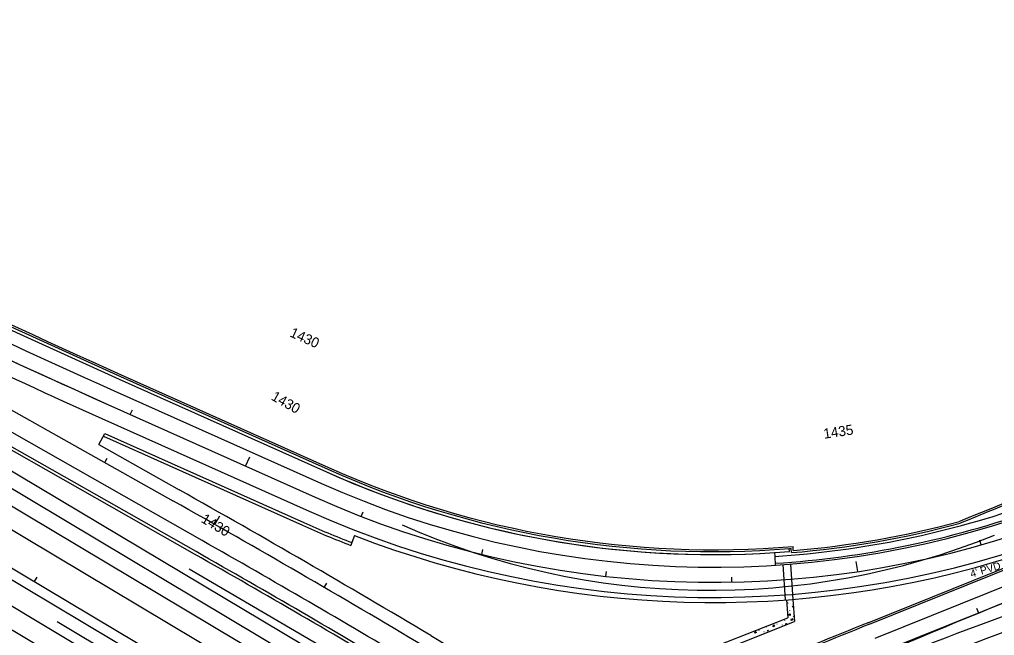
# Model space of a CAD drawing. Extents: x 2339272 to 2351734, y 366540 to 375057.
# Drawn here: x 2349008 to 2349780, y 368209 to 368697 of the extents above; entities that cross this region are included whole.
import ezdxf

# ---------------------------------------------------------------- set-up
doc = ezdxf.new("R2010")
doc.units = 0
for name, color, linetype in [('RD_HC_Cl', 7, 'Continuous'), ('RD_HC_CL_Rel', 7, 'Continuous'), ('RD_HC_Data_Tic', 7, 'Continuous'), ('RD_HC_Data_Tic_Rel', 7, 'Continuous'), ('RD_HC_TX_Rel_Sta50', 7, 'Continuous'), ('RD_HC_TX_Sta50', 7, 'Continuous'), ('RD_PD_Final_LnLine', 7, 'Continuous'), ('RD_PD_Final_TrvlWay', 7, 'Continuous'), ('RD_PD_FOC', 7, 'Continuous'), ('RD_PD_GR', 7, 'Continuous'), ('RD_PD_GrRail', 7, 'Continuous'), ('RD_PD_MedBWall', 7, 'Continuous'), ('RD_PD_MedGR', 7, 'Continuous'), ('RD_PD_NOISE-WALL-GM', 7, 'Continuous'), ('RD_PD_PaveShd', 7, 'Continuous'), ('RD_PD_SW', 7, 'Continuous'), ('RD_PD_WallCut', 7, 'Continuous')]:
    doc.layers.add(name, color=color, linetype=linetype)

msp = doc.modelspace()

# ---------------------------------------------------------------- linework, layer by layer
at = {"layer": 'RD_HC_Cl'}
msp.add_line((2346281.57, 369885.43), (2351112.4, 367003.22), dxfattribs=at)
for centre, radius, start, end in [((2351947.82, 362927.74), 5729.58, 109.588035, 115.940729), ((2349555.53, 368844.49), 600, 245.9774, 292.01473), ((2349555.53, 368844.49), 600, 245.9774, 292.01473), ((2349555.53, 368844.49), 600, 245.9774, 292.01473), ((2349555.53, 368844.49), 600, 245.9774, 292.01473)]:
    msp.add_arc(centre, radius, start, end, dxfattribs=at)
at = {"layer": 'RD_HC_CL_Rel'}
for p, q in [((2348500.93, 368669.16), (2349129.79, 368315.43)), ((2349078.31, 368391.71), (2349242.47, 368318.22))]:
    msp.add_line(p, q, dxfattribs=at)
for centre, radius, start, end in [((2351938.58, 374780.68), 7000, 240.642806, 245.882475), ((2344717.52, 360471.2), 9000, 59.178507, 60.642806), ((2349557.92, 369022.83), 772, 245.88247, 289.58804)]:
    msp.add_arc(centre, radius, start, end, dxfattribs=at)
at = {"layer": 'RD_HC_Data_Tic'}
for p, q in [((2349020.25, 368251.46), (2349022.3, 368254.89)), ((2349767.92, 368226.43), (2349766.4, 368230.13))]:
    msp.add_line(p, q, dxfattribs=at)
at = {"layer": 'RD_HC_Data_Tic_Rel'}
for p, q in [((2349096.07, 368383.76), (2349097.7, 368387.41)), ((2349187.34, 368342.9), (2349190.61, 368350.2)), ((2349075.82, 368345.78), (2349077.78, 368349.27)), ((2349162.94, 368296.69), (2349166.89, 368303.64)), ((2349279.01, 368302.97), (2349280.45, 368306.7)), ((2349769.8, 368280.48), (2349768.7, 368284.32)), ((2349374.33, 368272.98), (2349375.28, 368276.86)), ((2349672.13, 368259.33), (2349670.95, 368267.24)), ((2349472.73, 368255.55), (2349473.17, 368259.52)), ((2349249.62, 368246.81), (2349251.63, 368250.27)), ((2349572.55, 368250.97), (2349572.48, 368254.97))]:
    msp.add_line(p, q, dxfattribs=at)
at = {"layer": 'RD_PD_Final_LnLine'}
for p, q in [((2348620.92, 368538.62), (2351133.92, 367039.29)), ((2348577.88, 368466.48), (2351090.88, 366967.15)), ((2349078.31, 368391.71), (2349242.47, 368318.22)), ((2349612.85, 368264.87), (2349614.76, 368236.93)), ((2349618.83, 368265.28), (2349620.74, 368237.34)), ((2349685.87, 368206.54), (2349804.82, 368254.4)), ((2349690.35, 368195.41), (2349809.3, 368243.27))]:
    msp.add_line(p, q, dxfattribs=at)
for centre, radius, start, end in [((2351938.58, 374780.68), 7000, 239.178507, 245.882475), ((2349557.92, 369022.83), 772, 245.88247, 289.58804), ((2351783.35, 362853.29), 5729.58, 109.588035, 115.940729), ((2351783.35, 362853.29), 5717.58, 109.58804, 115.94073), ((2351783.35, 362853.29), 5705.58, 109.58804, 115.94073)]:
    msp.add_arc(centre, radius, start, end, dxfattribs=at)
at = {"layer": 'RD_PD_Final_TrvlWay'}
for p, q in [((2349153.03, 368283.92), (2348521.76, 368642.31)), ((2348626.93, 368549.01), (2350811.17, 367245.82)), ((2348827.21, 368485.63), (2349129.79, 368315.43)), ((2349083.21, 368402.66), (2349247.38, 368329.17)), ((2349073.41, 368380.76), (2349237.57, 368307.27)), ((2349681.39, 368217.67), (2349800.35, 368265.53))]:
    msp.add_line(p, q, dxfattribs=at)
for centre, radius, start, end in [((2351938.58, 374780.68), 6988, 239.178507, 245.882475), ((2351938.58, 374780.68), 7012, 243.703137, 245.882475), ((2349557.92, 369022.83), 760, 245.88247, 289.58804), ((2344717.52, 360471.2), 9000, 59.178507, 60.642806), ((2349557.92, 369022.83), 784, 245.88247, 289.58804), ((2344717.52, 360471.2), 8984, 59.178507, 60.415096), ((2351828.87, 362879.88), 5753.58, 111.915714, 113.768054)]:
    msp.add_arc(centre, radius, start, end, dxfattribs=at)
at = {"layer": 'RD_PD_FOC'}
msp.add_line((2349680.83, 368219.07), (2349799.79, 368266.92), dxfattribs=at)
for centre, radius, start, end in [((2349557.92, 369022.83), 758.5, 273.69192, 289.58804), ((2351828.87, 362879.88), 5755.08, 111.915714, 113.768054)]:
    msp.add_arc(centre, radius, start, end, dxfattribs=at)
at = {"layer": 'RD_PD_GR'}
for p, q in [((2349071, 368359.97), (2349134.69, 368324.14)), ((2349333.93, 368208.7), (2349381.89, 368180.08))]:
    msp.add_line(p, q, dxfattribs=at)
msp.add_arc((2344717.52, 360471.2), 9010, 59.178507, 60.642806, dxfattribs=at)
at = {"layer": 'RD_PD_GrRail'}
for p, q in [((2349142.77, 368261.41), (2349346.2, 368142.48)), ((2349038.24, 368219.76), (2349247.39, 368094.98))]:
    msp.add_line(p, q, dxfattribs=at)
at = {"layer": 'RD_PD_MedBWall'}
for p, q in [((2349087.3, 368411.79), (2349251.46, 368338.3)), ((2349088.25, 368413.92), (2349252.42, 368340.43)), ((2349618.15, 368275.25), (2349617.96, 368277.58))]:
    msp.add_line(p, q, dxfattribs=at)
for centre, radius, start, end in [((2351938.58, 374780.68), 6975.67, 239.178507, 245.882475), ((2351938.58, 374780.68), 6978, 239.178507, 245.882475), ((2349557.92, 369022.83), 750, 245.88247, 274.60618), ((2349557.92, 369022.83), 747.67, 245.88247, 274.60835)]:
    msp.add_arc(centre, radius, start, end, dxfattribs=at)
at = {"layer": 'RD_PD_MedGR'}
msp.add_line((2347144.89, 369361.04), (2349123.23, 368180.7), dxfattribs=at)
at = {"layer": 'RD_PD_NOISE-WALL-GM'}
for p, q in [((2349088.87, 368415.29), (2349253.03, 368341.8)), ((2349619.71, 368274.38), (2349619.48, 368277.7)), ((2349621.1, 368276), (2349620.88, 368279.32))]:
    msp.add_line(p, q, dxfattribs=at)
for centre, radius, start, end in [((2351938.58, 374780.68), 6974.17, 242.512616, 245.882475), ((2351947.82, 362927.74), 5802.58, 111.037339, 112.228758), ((2349557.92, 369022.83), 746.17, 245.88247, 274.84011), ((2351947.82, 362927.74), 5801.08, 111.052533, 112.229685), ((2349557.92, 369022.83), 751, 274.71968, 285.06835), ((2349557.92, 369022.83), 749.5, 274.83598, 285.06118), ((2349557.92, 369022.83), 747.67, 274.60618, 274.72329)]:
    msp.add_arc(centre, radius, start, end, dxfattribs=at)
at = {"layer": 'RD_PD_PaveShd'}
for p, q in [((2348633, 368559.35), (2349320.08, 368149.43)), ((2348612.75, 368524.86), (2349277.31, 368128.37)), ((2348586.11, 368480.2), (2349221.38, 368101.18)), ((2349087.3, 368411.79), (2349251.46, 368338.3)), ((2349071, 368359.97), (2349075.9, 368368.69)), ((2349075.9, 368368.69), (2349233.48, 368298.14)), ((2349071, 368359.97), (2349134.69, 368324.14)), ((2349273.69, 368287.88), (2349271.53, 368282.28)), ((2349606.18, 368274.39), (2349606.39, 368271.39)), ((2349333.93, 368208.7), (2349381.89, 368180.08))]:
    msp.add_line(p, q, dxfattribs=at)
for centre, radius, start, end in [((2351938.58, 374780.68), 6978, 239.178507, 245.882475), ((2349557.92, 369022.83), 750, 245.88247, 273.68943), ((2344717.52, 360471.2), 9010, 59.178507, 60.642806), ((2349557.92, 369022.83), 794, 245.88247, 248.85722), ((2349557.92, 369022.83), 788, 248.85722, 287.713), ((2344717.52, 360471.2), 8974, 59.178507, 60.415096)]:
    msp.add_arc(centre, radius, start, end, dxfattribs=at)
at = {"layer": 'RD_PD_SW'}
for p, q in [((2349606.39, 368271.39), (2349606.86, 368264.41)), ((2349615.76, 368236.96), (2349616.72, 368222.79)), ((2349616.91, 368234.66), (2349616.81, 368234.43)), ((2349620.74, 368237.34), (2349621.94, 368219.82)), ((2349618, 368228.67), (2349618.01, 368228.47)), ((2349522.02, 368185.49), (2349616.72, 368222.79)), ((2349522.76, 368180.29), (2349621.94, 368219.82)), ((2349614.25, 368221.24), (2349614.25, 368221.25)), ((2349614.38, 368220.35), (2349614.4, 368220.62)), ((2349619.52, 368220.68), (2349619.73, 368222.04)), ((2349620.92, 368223.86), (2349621.14, 368224.02)), ((2349593.94, 368212.52), (2349593.97, 368212.8)), ((2349597.81, 368211.99), (2349597.96, 368211.87)), ((2349599.94, 368215.3), (2349599.96, 368215.57)), ((2349608.38, 368217.58), (2349608.4, 368217.85)), ((2349612.24, 368217.04), (2349612.4, 368216.92)), ((2349585.51, 368210.25), (2349585.53, 368210.51))]:
    msp.add_line(p, q, dxfattribs=at)
for points in [[(2349620.25, 368231.41), (2349620.89, 368231.83), (2349621.16, 368231.19), (2349620.25, 368231.41)], [(2349617.32, 368225.14), (2349618.69, 368225.97), (2349618.52, 368224.55), (2349617.34, 368225.12)], [(2349619.95, 368222.07), (2349620.75, 368221.23), (2349619.55, 368220.69)], [(2349590.66, 368210.58), (2349590.9, 368212.16), (2349591.88, 368211.12), (2349590.68, 368210.59)], [(2349600.79, 368212.27), (2349600.88, 368213.04), (2349601.54, 368212.83), (2349600.79, 368212.27)], [(2349605.09, 368215.63), (2349605.33, 368217.21), (2349606.31, 368216.18), (2349605.12, 368215.64)], [(2349615.23, 368217.33), (2349615.31, 368218.09), (2349615.97, 368217.88), (2349615.23, 368217.33)]]:
    msp.add_lwpolyline(points, dxfattribs=at)
msp.add_arc((2349557.92, 369022.83), 753, 273.69032, 289.58804, dxfattribs=at)
at = {"layer": 'RD_PD_WallCut'}
for p, q in [((2349146.94, 368273.19), (2348627.08, 368568.34)), ((2349148.1, 368275.22), (2348628.23, 368570.36)), ((2349148.1, 368275.22), (2348628.23, 368570.36)), ((2349074.75, 368366.65), (2349232.53, 368296.01)), ((2349075.9, 368368.69), (2349233.48, 368298.14)), ((2349271.53, 368282.28), (2349270.69, 368280.1))]:
    msp.add_line(p, q, dxfattribs=at)
for centre, radius, start, end in [((2349557.92, 369022.83), 796.33, 245.88247, 248.85722), ((2349557.92, 369022.83), 794, 245.88247, 248.85722), ((2344717.52, 360471.2), 8971.67, 59.178507, 60.415096), ((2344717.52, 360471.2), 8974, 59.178507, 60.415096)]:
    msp.add_arc(centre, radius, start, end, dxfattribs=at)

# ---------------------------------------------------------------- texts
at = {"layer": 'RD_HC_TX_Rel_Sta50'}
for s, rotation, p in [('1430', 335.88247, (2349221.7, 368445.85)), ('1430', 330.40039, (2349206.99, 368395.88)), ('1435', 8.50784, (2349645.59, 368364.56))]:
    msp.add_text(s, height=8, rotation=rotation, dxfattribs=at).set_placement(p)
at = {"layer": 'RD_HC_TX_Sta50'}
msp.add_text('1430', height=8, rotation=329.17851, dxfattribs=at).set_placement((2349151.44, 368298.95))
at = {"layer": 'RD_PD_Final_TrvlWay'}
msp.add_text("4' PVD", height=6, rotation=16.3155, dxfattribs=at).set_placement((2349762.17, 368254.58))

doc.saveas('drawing.dxf')
